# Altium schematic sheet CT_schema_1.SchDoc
size 519 x 258 mm
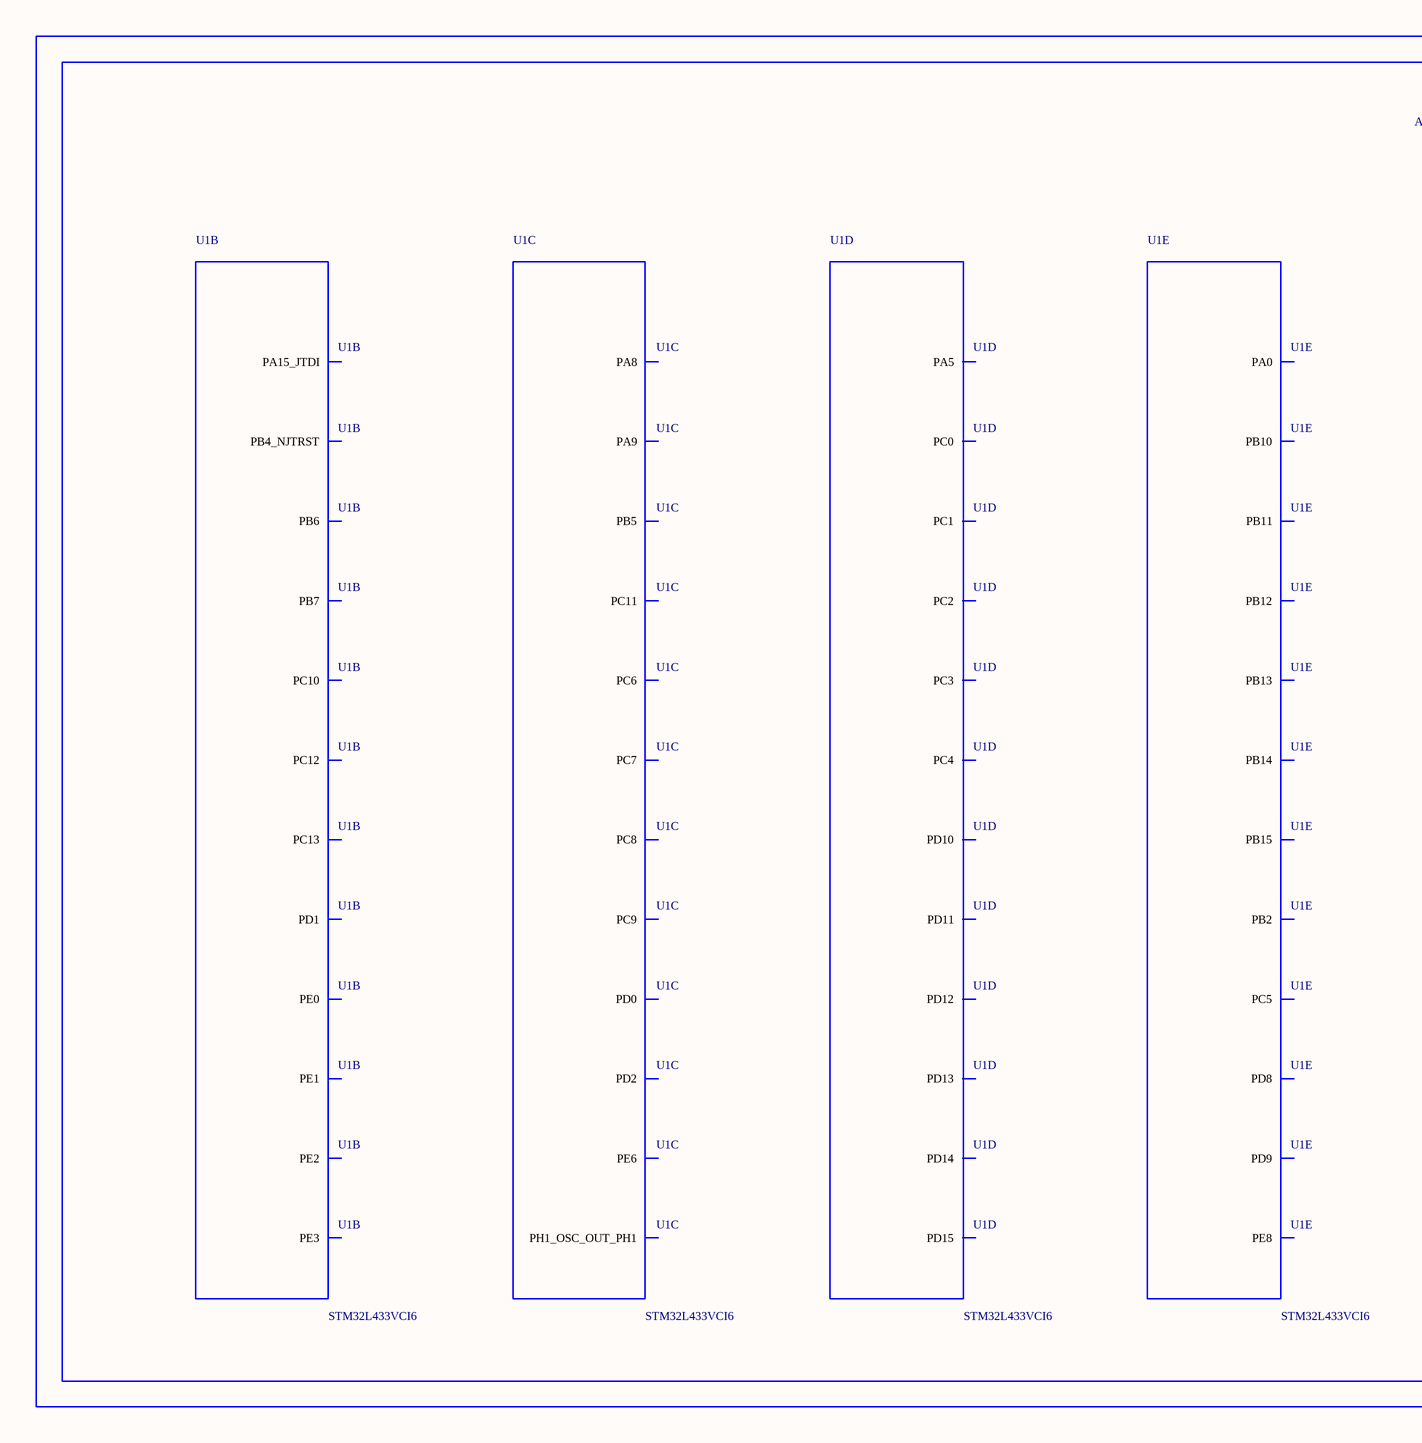
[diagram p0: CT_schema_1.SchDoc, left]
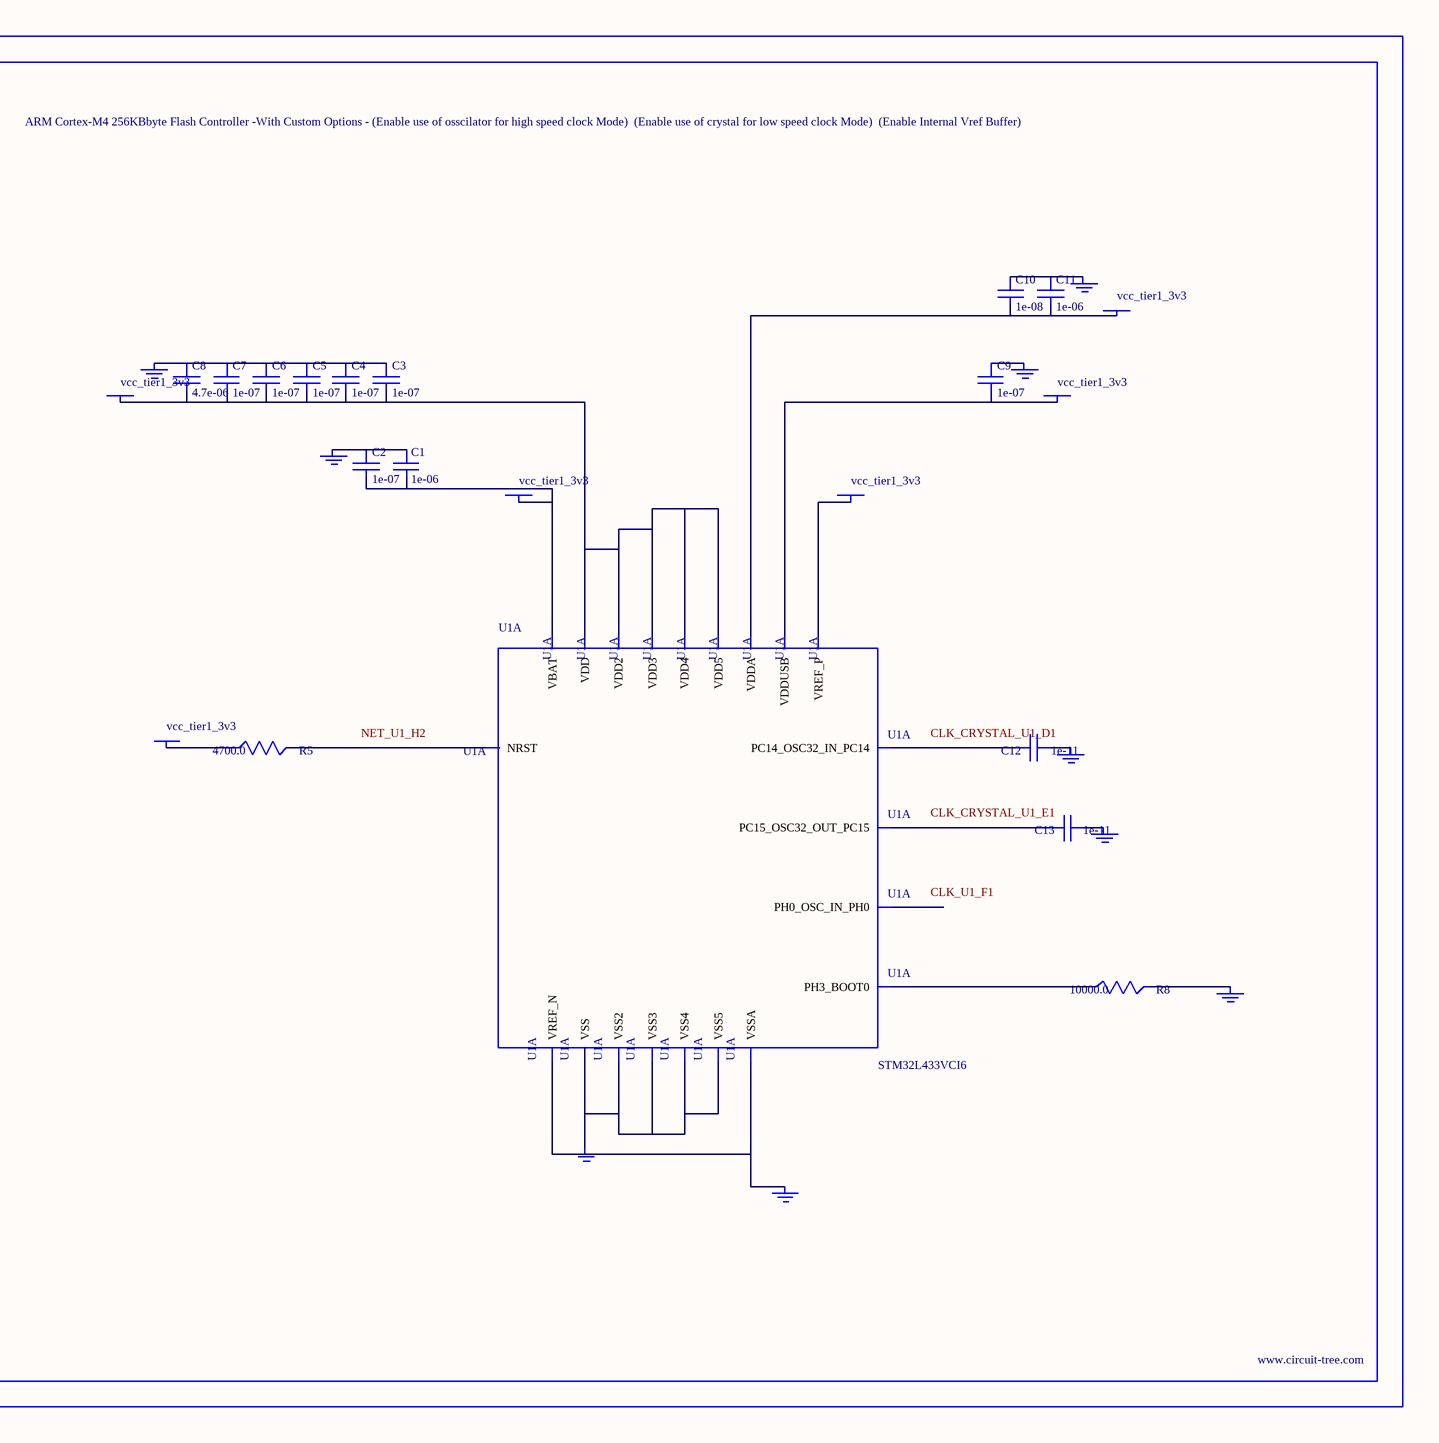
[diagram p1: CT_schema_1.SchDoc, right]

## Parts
BORDER0  (no value)
C1  1e-06  [C0603]
C2  1e-07  [C0603]
C3  1e-07  [C0603]
C4  1e-07  [C0603]
C5  1e-07  [C0603]
C6  1e-07  [C0603]
C7  1e-07  [C0603]
C8  4.7e-06  [C0603]
C9  1e-07  [C0603]
C10  1e-08  [C0603]
C11  1e-06  [C0603]
C12  1e-11  [C0402]
C13  1e-11  [C0402]
GND_INSTANCE_0_0  (no value)
GND_INSTANCE_0_1  (no value)
GND_INSTANCE_0_2  (no value)
GND_INSTANCE_0_3  (no value)
GND_INSTANCE_0_4  (no value)
GND_INSTANCE_0_5  (no value)
GND_INSTANCE_0_6  (no value)
GND_INSTANCE_0_7  (no value)
GND_INSTANCE_0_8  (no value)
POWER_INSTANCE_0_0  vcc_tier1_3v3
POWER_INSTANCE_0_1  vcc_tier1_3v3
POWER_INSTANCE_0_2  vcc_tier1_3v3
POWER_INSTANCE_0_3  vcc_tier1_3v3
POWER_INSTANCE_0_4  vcc_tier1_3v3
POWER_INSTANCE_0_5  vcc_tier1_3v3
R5  4700.0  [R0603]
R8  10000.0  [R0603]
U1  STM32L433VCI6  [UFBGA100]  (parts A,B,C,D,E of 11)

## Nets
NetC1_1: C1.1 C2.1 GND_INSTANCE_0_0.0(GND)
NetC1_2: C1.2 C2.2 POWER_INSTANCE_0_0.0(PWR) U1.E2(VBAT)
NetC3_1: C3.1 C4.1 C5.1 C6.1 C7.1 C8.1 GND_INSTANCE_0_1.0(GND)
NetC3_2: C3.2 C4.2 C5.2 C6.2 C7.2 C8.2 POWER_INSTANCE_0_1.0(PWR) U1.C4(VDD) U1.G2(VDD4) U1.G11(VDD2) U1.G12(VDD3) U1.H3(VDD5)
NetC9_1: C9.1 GND_INSTANCE_0_3.0(GND)
NetC9_2: C9.2 POWER_INSTANCE_0_2.0(PWR) U1.C11(VDDUSB)
NetC10_1: C10.1 C11.1 GND_INSTANCE_0_4.0(GND)
NetC10_2: C10.2 C11.2 POWER_INSTANCE_0_3.0(PWR) U1.M1(VDDA)
NetC12_1: C12.1 GND_INSTANCE_0_5.0(GND)
NetC12_2: C12.2 U1.D1(PC14_OSC32_IN_PC14)
NetC13_1: C13.1 GND_INSTANCE_0_6.0(GND)
NetC13_2: C13.2 U1.E1(PC15_OSC32_OUT_PC15)
NetGND_INSTANCE_0_2_0: GND_INSTANCE_0_2.0(GND) R8.2
NetGND_INSTANCE_0_7_0: GND_INSTANCE_0_7.0(GND) U1.J1(VSSA) U1.K1(VREF_N)
NetGND_INSTANCE_0_8_0: GND_INSTANCE_0_8.0(GND) U1.D3(VSS) U1.E3(VSS2) U1.F2(VSS5) U1.F11(VSS3) U1.F12(VSS4)
NetPOWER_INSTANCE_0_4_0: POWER_INSTANCE_0_4.0(PWR) U1.L1(VREF_P)
NetPOWER_INSTANCE_0_5_0: POWER_INSTANCE_0_5.0(PWR) R5.1
NetR5_2: R5.2 U1.H2(NRST)
NetR8_1: R8.1 U1.A4(PH3_BOOT0)

Not connected (* = marked no-connect by the designer): U1 A1(PE3) A2(PE1) A7(PB4_NJTRST) A9(PA15_JTDI) B2(PE2) B4(PB7) B5(PB6) B9(PD1) B10(PC12) B11(PC10) C1(PC13) C3(PE0) C5(PB5) C8(PD2) C9(PD0) C10(PC11) D2(PE6) D10(PA9) D11(PA8) D12(PC9) E10(PC8) E11(PC7) E12(PC6) F1(PH0_OSC_IN_PH0) G1(PH1_OSC_OUT_PH1) H1(PC0) H10(PD15) H11(PD14) H12(PD13) J2(PC1) J3(PC2) J10(PD12) J11(PD11) J12(PD10) K2(PC3) K4(PA5) K5(PC4) K8(PD9) K9(PD8) K10(PB15) K11(PB14) K12(PB13) L2(PA0) L5(PC5) L6(PB2) L7(PE8) L10(PB10) L11(PB11) L12(PB12)

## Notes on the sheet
- Labels drawn without touching a wire or pin: CLK_CRYSTAL_U1_D1, CLK_CRYSTAL_U1_E1, CLK_U1_F1, NET_U1_H2

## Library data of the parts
BORDER0 = BORDER_PAGE0
C1 C11 = C0603C105K3RACTU
C2-C7 C9 = 06035C104K4Z2A
C8 = GRM188R6YA475KE15D
C10 = 06035C103K4Z2A
C12 C13 = C0402C100K3GACTU
GND_INSTANCE_0_0-GND_INSTANCE_0_8 = GND
POWER_INSTANCE_0_0-POWER_INSTANCE_0_5 = PWR
R5 = RC0603JR-074K7L
R8 = RC0603JR-0710KL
